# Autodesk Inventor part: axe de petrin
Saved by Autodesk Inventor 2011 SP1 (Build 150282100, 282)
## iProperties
Created: 2010-12
Part Number: axe de petrin
Document SubType Name: Modeling
Designer: eric
Density: 1 g/cm^3
Mass: 2.69255 g
Surface Area: 14.7469 cm^2
Volume: 2.69255 cm^3
Author: eric
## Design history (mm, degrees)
feature "Base1"
node "Solide1"
node "Corps solides"
node "Corps surfaciques"
